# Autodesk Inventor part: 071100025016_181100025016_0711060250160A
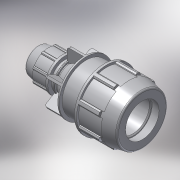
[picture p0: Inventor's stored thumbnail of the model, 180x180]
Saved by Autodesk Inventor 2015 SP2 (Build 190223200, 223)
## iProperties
Created: 2017-02
Part Number: 071100025016_181100025016_0711060250160A
Material: PVC-Piping
Description: PLASSON REDUCING COUPLER 25-16
Document SubType Name: Modeling
Designer: KIM
Mass: 92.6774 g
Surface Area: 199.44 cm^2
Volume: 66.1981 cm^3
Density: 1.4 g/cm^3
Appearance: Smooth - White
Author: KIM
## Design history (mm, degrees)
derived "07110.ipt"
feature "Solid1::07110.ipt"
tag "TaggingFeature1"
body "Solid1"
other parameters: "d2" = 25, "d4" = 9.41667, "d5" = 16.14286, "d7" = 54, "d9" = 16.14286, "d11" = 1.61429, "d12" = 43.2, "d13" = 120 deg, "d14" = 37.5, "d15" = 12 deg, "d16" = 48.6, "d18" = 1.25, "d19" = 35 deg, "d20" = 17.5 deg, "d21" = 50.22, "d23" = 0, "d25" = 360 deg, "d27" = 1.08, "d42" = 24.86, "d46" = 0.75, "d51" = 113, "d52" = 16.14286, "d53" = 12 deg, "d54" = 58, "d56" = 24, "d57" = 16, "d58" = 22.5, "d59" = 14.4, "d60" = 35.1, "d61" = 31.2, "d62" = 11.3, "d63" = 18.08, "d64" = 120 deg, "d65" = 39, "d68" = 8.07143, "d74" = 36.27, "d75" = 35 deg, "d76" = 17.5 deg, "d78" = 0, "d80" = 360 deg, "d85" = 0.78, "d88" = 0.32, "d94" = 37.8, "d97" = 2.28333, "d98" = 2.6, "d99" = 0, "d100" = 2.16, "d102" = 360 deg, "d104" = 2, "d106" = 0, "d107" = 2.6, "d108" = 0, "d109" = 2.6, "d110" = 0, "d_" = 25, "E_" = 54, "H_" = 113, "l_" = 58, "d_1" = 16, "E_1" = 39, "d96" = 6.85
